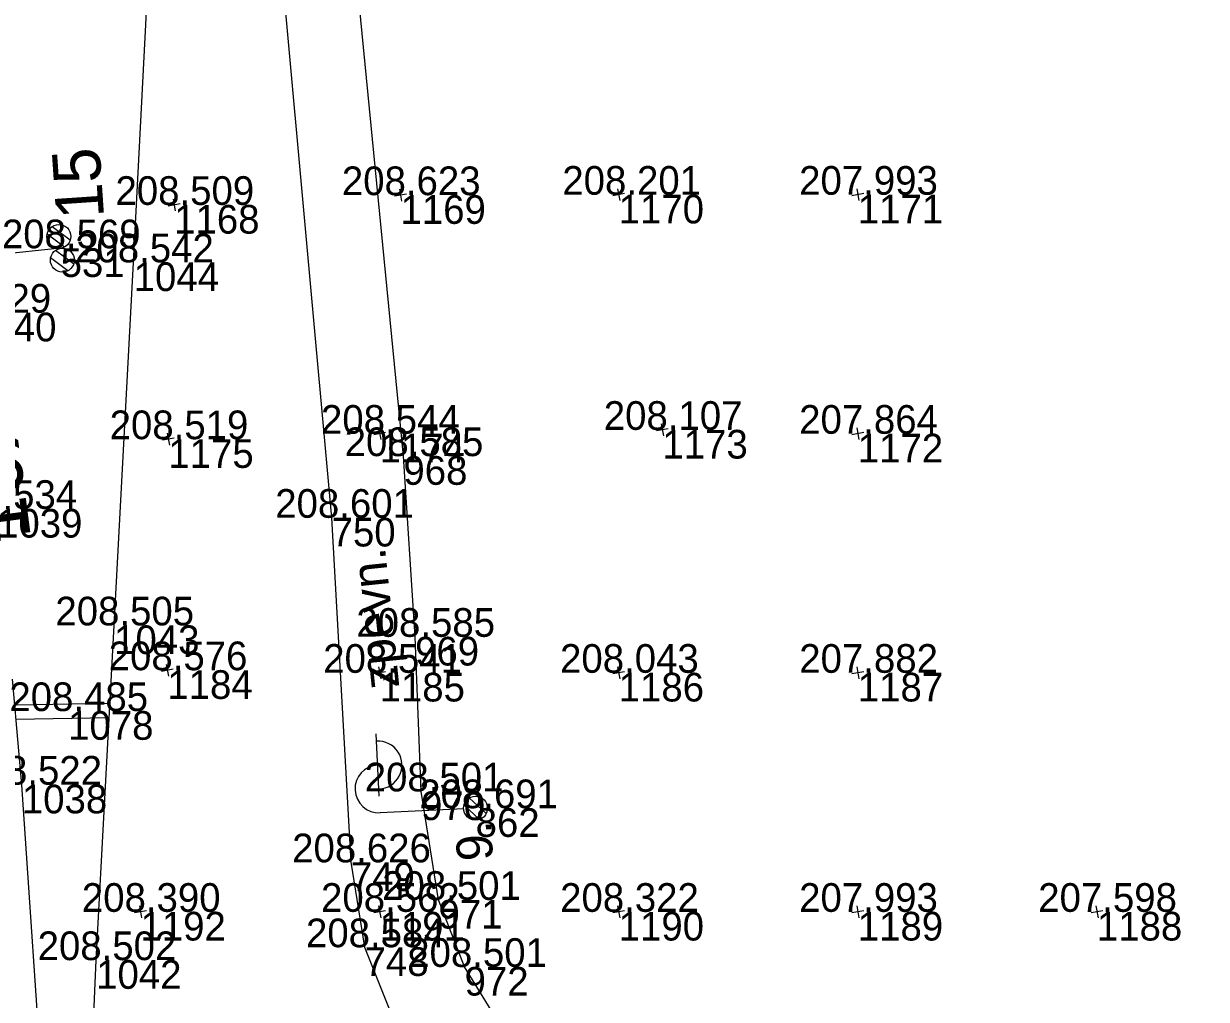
# Model space of a CAD drawing. Extents: x -556590 to -554855, y -1137918 to -1135717.
# Drawn here: x -554914.89 to -554865.42, y -1137683.66 to -1137642.84 of the extents above; entities that cross this region are included whole.
import ezdxf

# ---------------------------------------------------------------- set-up
doc = ezdxf.new("R2010")
doc.units = 0
for name, color, linetype in [('Vrstva 1', 7, 'Continuous'), ('Vrstva 11', 7, 'Continuous'), ('Vrstva 25', 7, 'Continuous'), ('Vrstva 49', 7, 'Continuous'), ('Vrstva 51', 7, 'Continuous'), ('Vrstva 60', 7, 'Continuous'), ('Vrstva 61', 7, 'Continuous'), ('Vrstva 7', 7, 'Continuous')]:
    doc.layers.add(name, color=color, linetype=linetype)

msp = doc.modelspace()

# ---------------------------------------------------------------- linework, layer by layer
at = {"layer": 'Vrstva 1'}
for points in [[(-554912.12, -1137717.809), (-554912.248, -1137715.711), (-554912.365, -1137713.967), (-554912.887, -1137706.122), (-554912.119, -1137688.223), (-554912.088, -1137687.497), (-554911.853, -1137682.02), (-554911.103, -1137668.018), (-554910.285, -1137652.829), (-554909.709, -1137641.532), (-554909.501, -1137632.959), (-554909.737, -1137623.526), (-554909.95, -1137619.461), (-554910.61, -1137610.419), (-554911.54, -1137597.875), (-554912.594, -1137582.977), (-554913.612, -1137568.149), (-554914.538, -1137554.794), (-554914.947, -1137549.002), (-554915.779, -1137537.195)], [(-554912.12, -1137717.809), (-554912.365, -1137713.967), (-554912.887, -1137706.122), (-554914.03, -1137688.41), (-554914.961, -1137674.68), (-554915.997, -1137663.144), (-554917.083, -1137654.934), (-554918.513, -1137646.457), (-554920.492, -1137634.952), (-554923.446, -1137618.62), (-554924.08, -1137609.374), (-554924.167, -1137608.122)]]:
    msp.add_lwpolyline(points, dxfattribs=at)
at = {"layer": 'Vrstva 11'}
for p, q in [((-554913.184, -1137652.188), (-554913.901, -1137651.653)), ((-554912.939, -1137651.902), (-554913.697, -1137651.337)), ((-554913.339, -1137652.24), (-554939.716, -1137654.957)), ((-554913.043, -1137653.18), (-554913.758, -1137652.646)), ((-554912.797, -1137652.896), (-554913.557, -1137652.328))]:
    msp.add_line(p, q, dxfattribs=at)
for centre in [(-554913.411, -1137651.745), (-554913.267, -1137652.735)]:
    msp.add_circle(centre, 0.5, dxfattribs=at)
at = {"layer": 'Vrstva 25'}
for p, q in [((-554900.013, -1137675.157), (-554900.137, -1137672.56)), ((-554895.536, -1137675.883), (-554896.245, -1137675.239)), ((-554896.483, -1137675.689), (-554899.979, -1137675.856)), ((-554895.815, -1137676.135), (-554896.466, -1137675.544))]:
    msp.add_line(p, q, dxfattribs=at)
msp.add_circle((-554895.984, -1137675.665), 0.5, dxfattribs=at)
for centre, start, end in [((-554900.063, -1137673.858), 272.0378, 93.4429), ((-554900.027, -1137674.857), 92.7403, 272.7403)]:
    msp.add_arc(centre, 1, start, end, dxfattribs=at)
at = {"layer": 'Vrstva 49'}
for p, q in [((-554908.638, -1137650.18), (-554908.544, -1137650.672)), ((-554898.879, -1137649.971), (-554899.371, -1137650.065)), ((-554899.172, -1137649.772), (-554899.078, -1137650.264)), ((-554889.754, -1137649.953), (-554890.246, -1137650.047)), ((-554890.047, -1137649.754), (-554889.953, -1137650.246)), ((-554879.754, -1137649.953), (-554880.246, -1137650.047)), ((-554880.047, -1137649.754), (-554879.953, -1137650.246)), ((-554908.345, -1137650.379), (-554908.837, -1137650.473)), ((-554908.882, -1137659.981), (-554908.788, -1137660.473)), ((-554899.754, -1137659.953), (-554900.246, -1137660.047)), ((-554900.047, -1137659.754), (-554899.953, -1137660.246)), ((-554887.926, -1137659.79), (-554888.418, -1137659.884)), ((-554888.219, -1137659.591), (-554888.125, -1137660.083)), ((-554879.754, -1137659.953), (-554880.246, -1137660.047)), ((-554880.047, -1137659.754), (-554879.953, -1137660.246)), ((-554908.589, -1137660.18), (-554909.081, -1137660.274)), ((-554908.631, -1137669.845), (-554909.123, -1137669.939)), ((-554908.924, -1137669.646), (-554908.83, -1137670.138)), ((-554899.754, -1137669.953), (-554900.246, -1137670.047)), ((-554900.047, -1137669.754), (-554899.953, -1137670.246)), ((-554889.754, -1137669.953), (-554890.246, -1137670.047)), ((-554890.047, -1137669.754), (-554889.953, -1137670.246)), ((-554879.754, -1137669.953), (-554880.246, -1137670.047)), ((-554880.047, -1137669.754), (-554879.953, -1137670.246)), ((-554910.047, -1137679.754), (-554909.953, -1137680.246)), ((-554900.047, -1137679.754), (-554899.953, -1137680.246)), ((-554890.047, -1137679.754), (-554889.953, -1137680.246)), ((-554880.047, -1137679.754), (-554879.953, -1137680.246)), ((-554870.047, -1137679.754), (-554869.953, -1137680.246)), ((-554909.754, -1137679.953), (-554910.246, -1137680.047)), ((-554899.754, -1137679.953), (-554900.246, -1137680.047)), ((-554889.754, -1137679.953), (-554890.246, -1137680.047)), ((-554879.754, -1137679.953), (-554880.246, -1137680.047)), ((-554869.754, -1137679.953), (-554870.246, -1137680.047))]:
    msp.add_line(p, q, dxfattribs=at)
at = {"layer": 'Vrstva 51'}
for points in [[(-554923.958, -1137439.154), (-554921.384, -1137460.492), (-554920.249, -1137473.563), (-554918.745, -1137491.257), (-554915.318, -1137516.028), (-554914.46, -1137526.509), (-554912.018, -1137566.83), (-554909.54, -1137599.474), (-554906.296, -1137619.179), (-554904.054, -1137640.988), (-554902.007, -1137663.515), (-554901.204, -1137677.928), (-554900.627, -1137681.481), (-554898.957, -1137685.66), (-554896.57, -1137689.296), (-554893.815, -1137691.613), (-554889.437, -1137693.47), (-554883.069, -1137697.253), (-554880.009, -1137699.781), (-554876.436, -1137704.84), (-554873.989, -1137710.204), (-554871.95, -1137718.337), (-554870.137, -1137731.24), (-554867.796, -1137750.715)], [(-554865.423, -1137750.912), (-554867.626, -1137732.718), (-554870.463, -1137713.797), (-554872.705, -1137706.486), (-554874.35, -1137702.628), (-554876.369, -1137699.594), (-554879.079, -1137696.932), (-554889.169, -1137689.933), (-554892.37, -1137687.595), (-554894.776, -1137685.019), (-554896.445, -1137682.304), (-554897.536, -1137679.501), (-554898.265, -1137674.962), (-554898.516, -1137668.495), (-554899.004, -1137660.935), (-554901.156, -1137638.823), (-554902.385, -1137618.708), (-554898.944, -1137616.157), (-554899.771, -1137604.198), (-554898.474, -1137602.261)]]:
    msp.add_lwpolyline(points, dxfattribs=at)
at = {"layer": 'Vrstva 60'}
for p, q in [((-554899.125, -1137650.018), (-554899.125, -1137650.018)), ((-554890, -1137650), (-554890, -1137650)), ((-554880, -1137650), (-554880, -1137650)), ((-554908.591, -1137650.426), (-554908.591, -1137650.426)), ((-554913.339, -1137652.24), (-554913.339, -1137652.24)), ((-554910.285, -1137652.829), (-554910.285, -1137652.829)), ((-554900, -1137660), (-554900, -1137660)), ((-554888.172, -1137659.837), (-554888.172, -1137659.837)), ((-554880, -1137660), (-554880, -1137660)), ((-554908.835, -1137660.227), (-554908.835, -1137660.227)), ((-554899.004, -1137660.935), (-554899.004, -1137660.935)), ((-554902.007, -1137663.515), (-554902.007, -1137663.515)), ((-554911.103, -1137668.018), (-554911.103, -1137668.018)), ((-554898.516, -1137668.495), (-554898.516, -1137668.495)), ((-554908.877, -1137669.892), (-554908.877, -1137669.892)), ((-554900, -1137670), (-554900, -1137670)), ((-554890, -1137670), (-554890, -1137670)), ((-554880, -1137670), (-554880, -1137670)), ((-554913.027, -1137671.602), (-554913.027, -1137671.602)), ((-554898.265, -1137674.962), (-554898.265, -1137674.962)), ((-554895.984, -1137675.665), (-554895.984, -1137675.665)), ((-554901.204, -1137677.928), (-554901.204, -1137677.928)), ((-554897.536, -1137679.501), (-554897.536, -1137679.501)), ((-554910, -1137680), (-554910, -1137680)), ((-554900, -1137680), (-554900, -1137680)), ((-554890, -1137680), (-554890, -1137680)), ((-554880, -1137680), (-554880, -1137680)), ((-554870, -1137680), (-554870, -1137680)), ((-554900.627, -1137681.481), (-554900.627, -1137681.481)), ((-554911.853, -1137682.02), (-554911.853, -1137682.02)), ((-554896.445, -1137682.304), (-554896.445, -1137682.304))]:
    msp.add_line(p, q, dxfattribs=at)
at = {"layer": 'Vrstva 7'}
for p, q in [((-554915.261, -1137671.342), (-554911.277, -1137671.27)), ((-554915.207, -1137671.941), (-554911.309, -1137671.871)), ((-554913.027, -1137671.602), (-554913.027, -1137671.602))]:
    msp.add_line(p, q, dxfattribs=at)

# ---------------------------------------------------------------- texts
at = {"layer": 'Vrstva 1'}
msp.add_text('10X', height=2.5, rotation=97.5352, dxfattribs=at).set_placement((-554914.574, -1137664.366))
at = {"layer": 'Vrstva 11'}
msp.add_text('15', height=2, rotation=93.861, dxfattribs=at).set_placement((-554911.519, -1137650.949))
at = {"layer": 'Vrstva 25'}
msp.add_text('9.', height=1.5, rotation=92.7403, dxfattribs=at).set_placement((-554895.257, -1137677.837))
at = {"layer": 'Vrstva 51'}
msp.add_text('zpevn.', height=1.5, rotation=95.8695, dxfattribs=at).set_placement((-554899.171, -1137670.602))
at = {"layer": 'Vrstva 60'}
for s, p in [('1169', (-554899.125, -1137651.218)), ('1170', (-554890, -1137651.2)), ('1171', (-554880, -1137651.2)), ('1168', (-554908.591, -1137651.626)), ('531', (-554913.339, -1137653.44)), ('1044', (-554910.285, -1137654.029)), ('1040', (-554917.083, -1137656.134)), ('1174', (-554900, -1137661.2)), ('1173', (-554888.172, -1137661.037)), ('1172', (-554880, -1137661.2)), ('1175', (-554908.835, -1137661.427)), ('968', (-554899.004, -1137662.135)), ('1039', (-554915.997, -1137664.344)), ('750', (-554902.007, -1137664.715)), ('1043', (-554911.103, -1137669.218)), ('969', (-554898.516, -1137669.695)), ('1184', (-554908.877, -1137671.092)), ('1185', (-554900, -1137671.2)), ('1186', (-554890, -1137671.2)), ('1187', (-554880, -1137671.2)), ('1078', (-554913.027, -1137672.802)), ('1038', (-554914.961, -1137675.88)), ('970', (-554898.265, -1137676.162)), ('862', (-554895.984, -1137676.865)), ('749', (-554901.204, -1137679.128)), ('971', (-554897.536, -1137680.701)), ('1192', (-554910, -1137681.2)), ('1191', (-554900, -1137681.2)), ('1190', (-554890, -1137681.2)), ('1189', (-554880, -1137681.2)), ('1188', (-554870, -1137681.2)), ('748', (-554900.627, -1137682.681)), ('1042', (-554911.853, -1137683.22)), ('972', (-554896.445, -1137683.504))]:
    msp.add_text(s, height=1.2, dxfattribs=at).set_placement(p)
at = {"layer": 'Vrstva 61'}
for s, p in [('208.623', (-554901.577, -1137650.018)), ('208.201', (-554892.357, -1137650)), ('207.993', (-554882.452, -1137650)), ('208.509', (-554911.045, -1137650.426)), ('208.569', (-554915.793, -1137652.24)), ('208.542', (-554912.733, -1137652.829)), ('208.529', (-554919.537, -1137654.934)), ('208.519', (-554911.289, -1137660.227)), ('208.544', (-554902.451, -1137660)), ('208.107', (-554890.624, -1137659.837)), ('207.864', (-554882.451, -1137660)), ('208.585', (-554901.46, -1137660.935)), ('208.534', (-554918.448, -1137663.144)), ('208.601', (-554904.364, -1137663.515)), ('208.505', (-554913.559, -1137668.018)), ('208.585', (-554900.972, -1137668.495)), ('208.576', (-554911.329, -1137669.892)), ('208.541', (-554902.357, -1137670)), ('208.043', (-554892.452, -1137670)), ('207.882', (-554882.448, -1137670)), ('208.485', (-554915.483, -1137671.602)), ('208.522', (-554917.409, -1137674.68)), ('208.501', (-554900.622, -1137674.962)), ('208.691', (-554898.341, -1137675.665)), ('208.626', (-554903.656, -1137677.928)), ('208.501', (-554899.893, -1137679.501)), ('208.390', (-554912.451, -1137680)), ('208.562', (-554902.448, -1137680)), ('208.322', (-554892.448, -1137680)), ('207.993', (-554882.452, -1137680)), ('207.598', (-554872.454, -1137680)), ('208.584', (-554903.078, -1137681.481)), ('208.502', (-554914.301, -1137682.02)), ('208.501', (-554898.802, -1137682.304))]:
    msp.add_text(s, height=1.2, dxfattribs=at).set_placement(p)

doc.saveas('drawing.dxf')
